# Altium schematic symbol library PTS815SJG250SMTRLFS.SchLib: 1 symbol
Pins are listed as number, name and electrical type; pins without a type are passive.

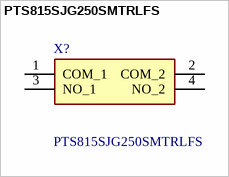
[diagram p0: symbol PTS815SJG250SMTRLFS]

## PTS815SJG250SMTRLFS
designator X?
Switch Tactile N.O. SPST Button J-Bend 0.05A 12VDC 3.92N SMD T/R; Manufacturer_Name: LITTELFUSE; Geometry.Height: 2.7mm
footprint PTS815SJG250SMTRLFS
pins: 1 COM_1, 2 COM_2, 3 NO_1, 4 NO_2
